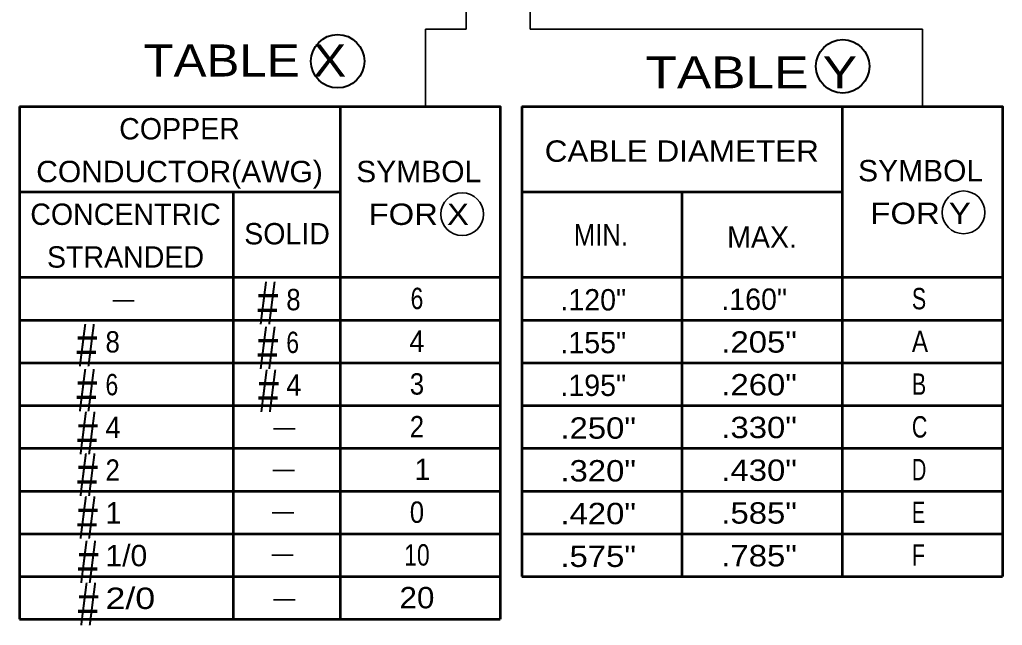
# Model space of a CAD drawing. Extents: x -1 to 679, y 0 to 440.
# Drawn here: x 86.8 to 178.8, y 78.2 to 134.9 of the extents above; entities that cross this region are included whole.
import ezdxf
from ezdxf.enums import TextEntityAlignment as Align

# ---------------------------------------------------------------- set-up
doc = ezdxf.new("R2010")
doc.units = 0
doc.header["$LTSCALE"] = 0.8
doc.layers.add('1', color=7, linetype='Continuous', lineweight=53)

msp = doc.modelspace()

# ---------------------------------------------------------------- linework, layer by layer
at = {"layer": '1', "lineweight": 35}
for p, q in [((128.6378, 137.9889), (128.6378, 134.0118)), ((134.6378, 137.9889), (134.6378, 134.0118)), ((128.6378, 134.0118), (124.8449, 134.0118)), ((124.8449, 134.0118), (124.8449, 126.7763)), ((134.6378, 134.0118), (171.3799, 134.0118)), ((171.3799, 134.0118), (171.3799, 126.7763)), ((95.553, 108.5783), (97.553, 108.5783)), ((110.6251, 96.5909), (112.6251, 96.5909)), ((110.5621, 92.7009), (112.5621, 92.7009)), ((110.5003, 88.7463), (112.5003, 88.7463)), ((110.4386, 84.7917), (112.4386, 84.7917)), ((110.6239, 80.5899), (112.6239, 80.5899))]:
    msp.add_line(p, q, dxfattribs=at)
at = {"layer": '1'}
for p, q in [((86.8449, 126.7763), (86.8449, 78.7763)), ((116.8449, 126.7763), (116.8449, 78.7763)), ((133.8449, 126.7763), (133.8449, 82.7763)), ((163.8449, 126.7763), (163.8449, 82.7763)), ((86.8449, 118.7763), (116.8449, 118.7763)), ((106.8449, 118.7763), (106.8449, 78.7763)), ((133.8449, 118.7763), (163.8449, 118.7763)), ((148.8449, 118.7763), (148.8449, 82.7763)), ((86.8449, 110.7763), (131.8449, 110.7763)), ((133.8449, 110.7763), (178.8449, 110.7763)), ((86.8449, 106.7763), (131.8449, 106.7763)), ((133.8449, 106.7763), (178.8449, 106.7763)), ((86.8449, 102.7763), (131.8449, 102.7763)), ((133.8449, 102.7763), (178.8449, 102.7763)), ((86.8449, 98.7763), (131.8449, 98.7763)), ((133.8449, 98.7763), (178.8449, 98.7763)), ((86.8449, 94.7763), (131.8449, 94.7763)), ((133.8449, 94.7763), (178.8449, 94.7763)), ((86.8449, 90.7763), (131.8449, 90.7763)), ((133.8449, 90.7763), (178.8449, 90.7763)), ((86.8449, 86.7763), (131.8449, 86.7763)), ((133.8449, 86.7763), (178.8449, 86.7763)), ((86.8449, 82.7763), (131.8449, 82.7763)), ((133.8449, 82.7763), (178.8449, 82.7763)), ((86.8449, 78.7763), (131.8449, 78.7763))]:
    msp.add_line(p, q, dxfattribs=at)
for points in [[(86.8449, 126.7763), (131.8449, 126.7763), (131.8449, 78.7763)], [(133.8449, 126.7763), (178.8449, 126.7763), (178.8449, 82.7763)]]:
    msp.add_lwpolyline(points, dxfattribs=at)
at = {"layer": '1', "lineweight": 40}
for centre in [(116.614, 130.9928), (163.8966, 130.5235)]:
    msp.add_circle(centre, 2.5, dxfattribs=at)
at = {"layer": '1', "lineweight": 35}
for centre in [(128.2683, 116.6801), (175.2159, 116.8552)]:
    msp.add_circle(centre, 2, dxfattribs=at)

# ---------------------------------------------------------------- texts
at = {"layer": '1'}
for s, height, width, p in [('TABLE X', 3, 1.15, (98.4417, 129.567)), ('TABLE Y', 3, 1.2, (145.4382, 128.4553)), ('CABLE DIAMETER', 2, 1.1, (136.0026, 121.5884)), ('MIN.', 2, 0.9, (138.722, 113.7541)), ('#', 4, 0.65, (109.1012, 106.3875)), ('8', 2, 0.9, (111.8092, 107.6933)), ('S', 2, 0.75, (170.3754, 107.7825)), ('#', 4, 0.65, (92.1761, 102.4329)), ('#', 4, 0.65, (109.1012, 102.1857)), ('8', 2, 0.9, (94.8841, 103.7387)), ('6', 2, 0.8, (111.8092, 103.6933)), ('.205"', 2, 1.15, (152.5363, 103.7281)), ('A', 2, 0.85, (170.3754, 103.7825)), ('#', 4, 0.65, (92.1761, 98.2312)), ('#', 4, 0.65, (109.163, 98.1693)), ('6', 2, 0.8, (94.8841, 99.7387)), ('4', 2, 0.95, (111.8092, 99.6933)), ('.260"', 2, 1.15, (152.5363, 99.7281)), ('B', 2, 0.75, (170.3754, 99.7825)), ('#', 4, 0.65, (92.2378, 94.2147)), ('4', 2, 0.95, (94.8841, 95.7387)), ('.250"', 2, 1.15, (137.4711, 95.6737)), ('.330"', 2, 1.15, (152.5363, 95.7281)), ('C', 2, 0.75, (170.3754, 95.7825)), ('#', 4, 0.65, (92.2378, 90.322)), ('2', 2, 0.9, (94.8841, 91.7387)), ('.320"', 2, 1.15, (137.4711, 91.6737)), ('.430"', 2, 1.15, (152.5363, 91.7281)), ('D', 2, 0.7, (170.3754, 91.7825)), ('#', 4, 0.65, (92.2378, 86.3056)), ('.420"', 2, 1.15, (137.4711, 87.6737)), ('.585"', 2, 1.15, (152.5363, 87.7281)), ('E', 2, 0.7, (170.3754, 87.7825)), ('#', 4, 0.65, (92.2996, 82.1656)), ('1/0', 2, 1.05, (94.8841, 83.7387)), ('.575"', 2, 1.15, (137.4711, 83.6737)), ('.785"', 2, 1.15, (152.5363, 83.7281)), ('F', 2, 0.75, (170.3754, 83.7825)), ('#', 4, 0.65, (92.2996, 78.211)), ('2/0', 2, 1.25, (94.8841, 79.7387))]:
    msp.add_text(s, height=height, dxfattribs=dict(at, width=width)).set_placement(p)
for s, p in [('COPPER', (101.8117, 123.6776)), ('CONCENTRIC', (96.7567, 115.6809)), ('STRANDED', (96.7566, 111.6809)), ('1', (124.5537, 91.8017))]:
    msp.add_text(s, height=2, dxfattribs=at).set_placement(p, align=Align.CENTER)
for s, width, p in [('CONDUCTOR(AWG)', 1.05, (101.8117, 119.6776)), ('SYMBOL', 1.05, (124.2066, 119.6792)), ('SYMBOL', 1.05, (171.1913, 119.7593)), ('FOR Y', 1.15, (171.1912, 115.7593)), ('FOR X', 1.15, (124.2065, 115.6792)), ('6', 0.8, (124.0398, 107.8017)), ('4', 0.95, (124.0397, 103.8017)), ('3', 0.9, (124.0398, 99.8017)), ('2', 0.9, (124.0398, 95.8017)), ('0', 0.9, (124.0398, 87.8017)), ('10', 0.8, (124.0398, 83.8017)), ('20', 1.1, (124.0397, 79.8017))]:
    msp.add_text(s, height=2, dxfattribs=dict(at, width=width)).set_placement(p, align=Align.CENTER)
for s, p in [('SOLID', (107.8659, 113.8577)), ('MAX.', (153.0803, 113.5364)), ('.120"', (137.4711, 107.6737)), ('.160"', (152.5363, 107.7281)), ('.155"', (137.4711, 103.6737)), ('.195"', (137.4711, 99.6737)), ('1', (94.8841, 87.7387))]:
    msp.add_text(s, height=2, dxfattribs=at).set_placement(p)

doc.saveas('drawing.dxf')
